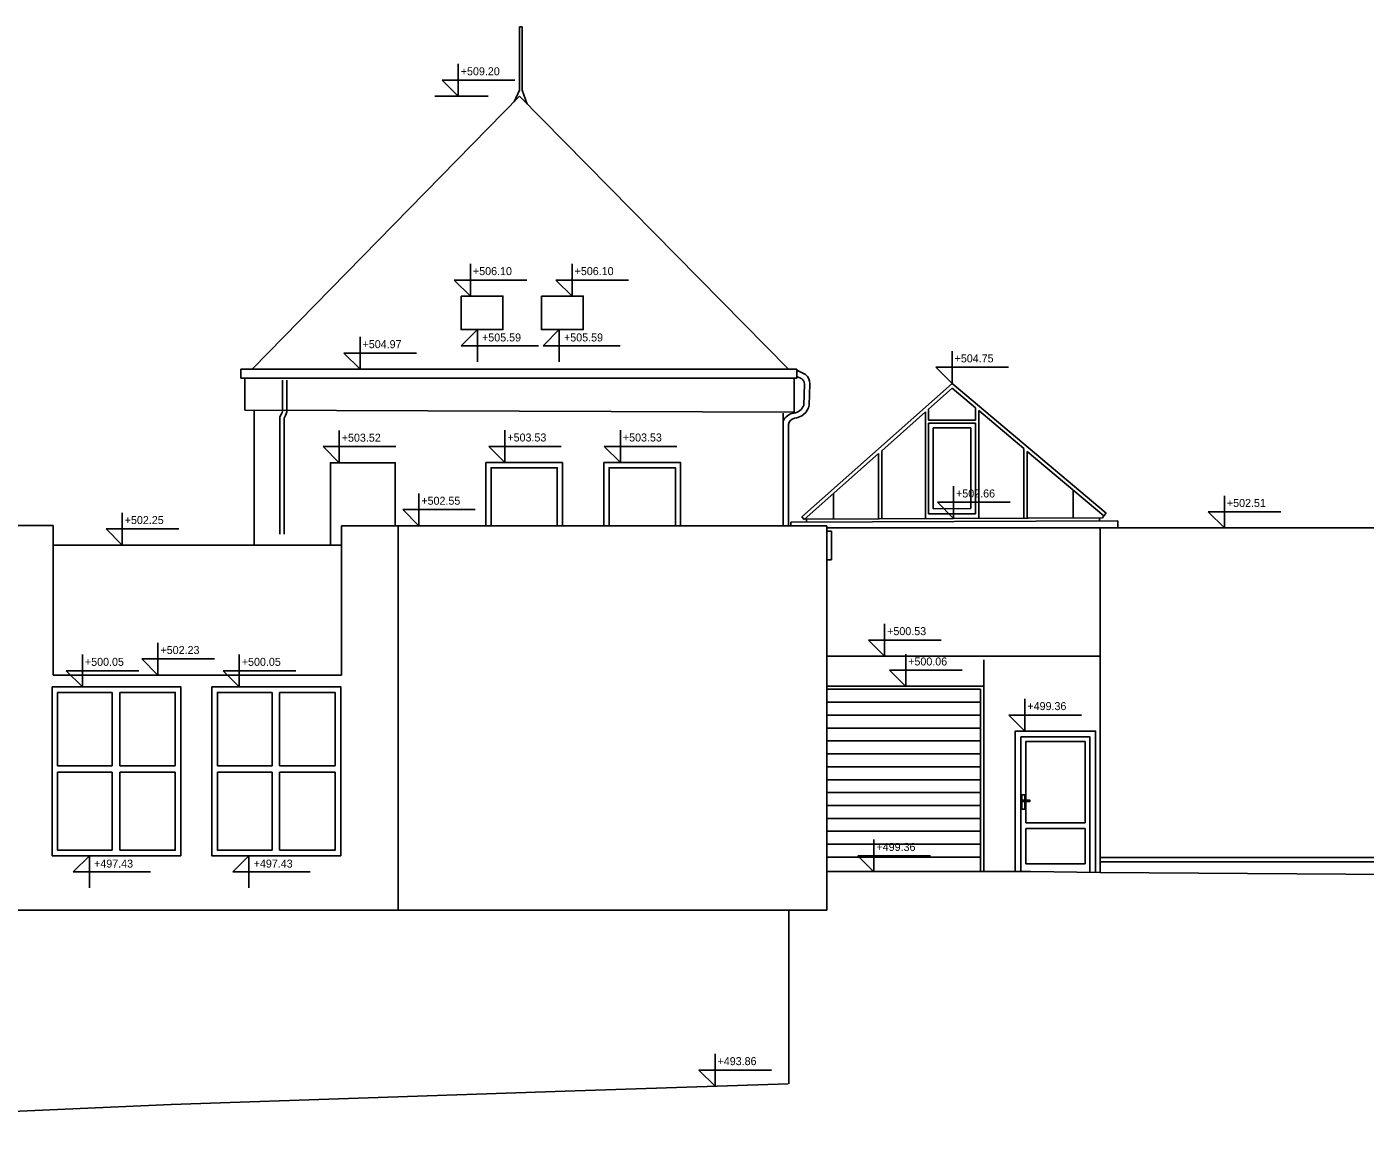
# Model space of a CAD drawing. Extents: x 224 to 311.2, y 493.1 to 511.4.
# Drawn here: x 243.47 to 264.21, y 493.15 to 510.28 of the extents above; entities that cross this region are included whole.
import ezdxf

# ---------------------------------------------------------------- set-up
doc = ezdxf.new("R2010")
doc.units = 0
for name, color, linetype in [('antena', 7, 'Continuous'), ('dvere', 7, 'Continuous'), ('okap', 7, 'Continuous'), ('okna', 7, 'Continuous'), ('strecha_sikma', 7, 'Continuous'), ('svetlik', 7, 'Continuous'), ('teren', 7, 'Continuous'), ('zakl_tenka', 7, 'Continuous'), ('zebrik', 7, 'Continuous'), ('znaceni', 7, 'Continuous')]:
    doc.layers.add(name, color=color, linetype=linetype)

msp = doc.modelspace()

# ---------------------------------------------------------------- linework, layer by layer
at = {"layer": 'antena'}
for p, q in [((251.102, 509.297), (251.102, 510.277)), ((251.142, 510.277), (251.142, 509.297)), ((251.017, 509.115), (251.102, 509.297)), ((251.142, 509.297), (251.222, 509.076))]:
    msp.add_line(p, q, dxfattribs=at)
at = {"layer": 'dvere'}
for p, q in [((257.511, 504.062), (257.511, 502.809)), ((257.511, 504.062), (258.096, 504.062)), ((258.096, 504.062), (258.096, 502.811)), ((258.096, 502.811), (257.511, 502.809)), ((255.862, 500.011), (258.244, 500.011)), ((258.244, 500.011), (258.244, 497.186)), ((255.862, 499.811), (258.244, 499.811)), ((255.862, 499.611), (258.244, 499.611)), ((255.862, 499.411), (258.244, 499.411)), ((255.862, 499.211), (258.244, 499.211)), ((255.862, 499.011), (258.244, 499.011)), ((255.862, 498.811), (258.244, 498.811)), ((255.862, 498.611), (258.244, 498.611)), ((255.862, 498.411), (258.244, 498.411)), ((255.862, 498.211), (258.244, 498.211)), ((255.862, 498.011), (258.244, 498.011)), ((255.862, 497.811), (258.244, 497.811)), ((258.945, 497.945), (259.864, 497.945)), ((258.945, 497.855), (259.864, 497.855)), ((255.862, 497.611), (258.244, 497.611)), ((255.862, 497.411), (258.244, 497.411)), ((258.945, 497.308), (259.864, 497.308))]:
    msp.add_line(p, q, dxfattribs=at)
for points in [[(248.172, 502.246), (248.172, 503.522), (249.175, 503.522), (249.175, 502.545)], [(258.871, 497.186), (258.871, 499.275), (259.939, 499.275), (259.939, 497.176)], [(258.945, 498.296), (258.945, 499.201), (259.864, 499.201), (259.864, 497.945)], [(258.933, 498.272), (258.933, 498.153), (258.887, 498.153), (258.887, 498.377), (258.933, 498.377), (258.933, 498.296)], [(258.945, 497.945), (258.945, 498.272)], [(258.945, 497.308), (258.945, 497.855)], [(259.864, 497.855), (259.864, 497.308)]]:
    msp.add_lwpolyline(points, dxfattribs=at)
msp.add_lwpolyline([(258.901, 498.296), (259.008, 498.296), (259.008, 498.272), (258.901, 498.272)], close=True, dxfattribs=at)
at = {"layer": 'okap'}
for p, q in [((255.399, 504.971), (246.784, 504.971)), ((246.784, 504.971), (246.784, 504.831)), ((255.399, 504.831), (246.784, 504.831)), ((255.399, 504.971), (255.399, 504.831)), ((255.399, 504.958), (255.534, 504.888)), ((255.399, 504.86), (255.478, 504.822)), ((247.43, 504.801), (247.43, 504.342)), ((247.497, 504.801), (247.497, 504.342)), ((255.516, 504.744), (255.505, 504.41)), ((255.602, 504.745), (255.592, 504.412)), ((247.386, 504.197), (247.386, 502.847)), ((247.453, 504.197), (247.453, 502.847)), ((255.27, 504.116), (255.27, 502.545)), ((247.386, 502.847), (247.386, 502.415)), ((247.453, 502.847), (247.453, 502.415))]:
    msp.add_line(p, q, dxfattribs=at)
for centre, radius, start, end in [((255.411, 504.742), 0.104, 0.9921, 50.0332), ((255.411, 504.742), 0.191, 0.9921, 50.0332), ((255.335, 504.471), 0.18, 275.4897, 340.1945), ((255.333, 504.475), 0.266, 275.7615, 346.155), ((247.493, 504.202), 0.108, 145.3455, 182.5261), ((247.282, 504.345), 0.148, 326.2232, 358.5303), ((247.493, 504.202), 0.0403, 145.3455, 182.5261), ((247.282, 504.345), 0.216, 326.2232, 358.5303), ((255.384, 504.073), 0.221, 98.3115, 154.5351), ((255.374, 504.107), 0.104, 97.5209, 175.263)]:
    msp.add_arc(centre, radius, start, end, dxfattribs=at)
at = {"layer": 'okna'}
for p, q in [((244.789, 499.964), (244.789, 498.825)), ((244.906, 499.964), (244.906, 498.825)), ((247.266, 499.964), (247.266, 498.825)), ((247.382, 499.964), (247.382, 498.825)), ((244.789, 498.825), (243.943, 498.825)), ((245.767, 498.825), (244.906, 498.825)), ((247.266, 498.825), (246.419, 498.825)), ((248.244, 498.825), (247.382, 498.825)), ((244.789, 498.73), (243.943, 498.73)), ((244.789, 498.73), (244.789, 497.519)), ((244.906, 498.73), (244.906, 497.519)), ((245.767, 498.73), (244.906, 498.73)), ((247.266, 498.73), (246.419, 498.73)), ((247.266, 498.73), (247.266, 497.519)), ((247.382, 498.73), (247.382, 497.519)), ((248.244, 498.73), (247.382, 498.73))]:
    msp.add_line(p, q, dxfattribs=at)
for points in [[(250.196, 506.103), (250.844, 506.103), (250.844, 505.585), (250.196, 505.585)], [(251.44, 506.103), (252.088, 506.103), (252.088, 505.585), (251.44, 505.585)]]:
    msp.add_lwpolyline(points, close=True, dxfattribs=at)
for points in [[(250.66, 502.545), (250.66, 503.445), (251.687, 503.445), (251.687, 502.545)], [(252.49, 502.545), (252.49, 503.445), (253.517, 503.445), (253.517, 502.545)], [(243.943, 498.825), (243.943, 499.964), (244.789, 499.964)], [(244.906, 499.964), (245.767, 499.964), (245.767, 498.825)], [(246.419, 498.825), (246.419, 499.964), (247.266, 499.964)], [(247.382, 499.964), (248.244, 499.964), (248.244, 498.825)], [(244.789, 497.519), (243.943, 497.519), (243.943, 498.73)], [(245.767, 498.73), (245.767, 497.519), (244.906, 497.519)], [(247.266, 497.519), (246.419, 497.519), (246.419, 498.73)], [(248.244, 498.73), (248.244, 497.519), (247.382, 497.519)]]:
    msp.add_lwpolyline(points, dxfattribs=at)
at = {"layer": 'strecha_sikma'}
for p, q in [((251.1, 509.2), (246.958, 504.971)), ((255.27, 504.971), (251.1, 509.2)), ((243.874, 502.246), (248.344, 502.246)), ((243.874, 500.233), (248.344, 500.233))]:
    msp.add_line(p, q, dxfattribs=at)
at = {"layer": 'svetlik'}
for p, q in [((257.804, 504.751), (255.476, 502.682)), ((257.804, 504.676), (257.44, 504.353)), ((257.804, 504.751), (260.192, 502.742)), ((257.804, 504.676), (258.167, 504.371)), ((257.39, 504.308), (256.713, 503.707)), ((257.39, 504.308), (257.39, 502.657)), ((257.44, 504.353), (257.44, 504.184)), ((258.167, 504.371), (258.167, 504.184)), ((258.217, 504.329), (258.217, 502.66)), ((258.217, 504.329), (258.917, 503.74)), ((257.44, 504.184), (258.167, 504.184)), ((257.44, 504.134), (258.167, 504.134)), ((257.44, 504.134), (257.44, 502.728)), ((258.167, 504.134), (258.167, 502.731)), ((256.663, 503.663), (255.513, 502.64)), ((256.663, 503.663), (256.663, 502.654)), ((256.713, 503.707), (256.713, 502.654)), ((258.917, 503.74), (258.917, 502.663)), ((258.967, 503.698), (258.967, 502.663)), ((258.967, 503.698), (260.155, 502.698)), ((255.965, 503.042), (255.965, 502.651)), ((259.681, 503.097), (259.681, 502.666)), ((260.155, 502.698), (260.192, 502.742)), ((255.476, 502.682), (255.513, 502.64)), ((258.167, 502.731), (257.44, 502.728))]:
    msp.add_line(p, q, dxfattribs=at)
at = {"layer": 'teren'}
for points in [[(255.862, 497.186), (259.02, 497.186), (260.099, 497.175)], [(260.099, 497.175), (263.904, 497.145), (275.27, 497.123), (276.223, 497.121), (292.012, 497.161), (304.698, 497.168)], [(255.262, 493.898), (251.81, 493.787), (245.706, 493.58), (242.767, 493.449), (242.495, 493.427), (237.49, 493.149)]]:
    msp.add_lwpolyline(points, dxfattribs=at)
at = {"layer": 'zakl_tenka'}
for p, q in [((246.844, 504.831), (246.844, 504.338)), ((255.359, 504.831), (255.359, 504.307)), ((255.359, 504.307), (246.844, 504.338)), ((246.992, 504.338), (246.992, 502.246)), ((255.185, 504.29), (255.185, 502.545)), ((236.111, 502.549), (243.874, 502.549)), ((243.874, 502.549), (243.874, 500.233)), ((248.344, 502.545), (248.344, 500.233)), ((255.862, 502.545), (248.344, 502.545)), ((249.221, 502.545), (249.221, 496.588)), ((260.371, 502.623), (255.304, 502.601)), ((255.304, 502.601), (255.304, 502.545)), ((260.133, 502.668), (255.523, 502.649)), ((255.548, 502.651), (255.548, 502.602)), ((255.862, 502.545), (255.862, 496.588)), ((260.086, 502.621), (260.086, 502.668)), ((260.133, 502.668), (260.155, 502.698)), ((260.371, 502.511), (260.371, 502.623)), ((255.862, 502.511), (267.643, 502.511)), ((255.937, 502.464), (255.862, 502.464)), ((255.937, 502.016), (255.937, 502.464)), ((260.099, 502.511), (260.099, 497.175)), ((255.862, 502.016), (255.937, 502.016)), ((255.862, 500.525), (260.099, 500.525)), ((258.294, 500.47), (258.294, 497.186)), ((255.862, 500.061), (258.294, 500.061)), ((260.099, 497.405), (289.987, 497.405)), ((260.099, 497.339), (289.987, 497.339)), ((242.413, 496.588), (255.862, 496.588)), ((255.275, 496.588), (255.275, 493.899))]:
    msp.add_line(p, q, dxfattribs=at)
for points in [[(250.58, 502.545), (250.58, 503.525), (251.767, 503.525), (251.767, 502.545)], [(252.41, 502.545), (252.41, 503.525), (253.597, 503.525), (253.597, 502.545)], [(258.783, 497.186), (258.783, 499.363), (260.027, 499.363), (260.027, 497.176)]]:
    msp.add_lwpolyline(points, dxfattribs=at)
for points in [[(243.857, 500.05), (245.853, 500.05), (245.853, 497.433), (243.857, 497.433)], [(246.333, 500.05), (248.33, 500.05), (248.33, 497.433), (246.333, 497.433)]]:
    msp.add_lwpolyline(points, close=True, dxfattribs=at)
at = {"layer": 'zebrik'}
msp.add_line((251.102, 510.277), (251.142, 510.277), dxfattribs=at)
at = {"layer": 'znaceni'}
for p, q in [((250.152, 509.7), (250.152, 509.2)), ((250.152, 509.45), (249.902, 509.45)), ((249.902, 509.45), (250.152, 509.2)), ((250.152, 509.45), (251.027, 509.45)), ((250.152, 509.2), (250.152, 509.45)), ((250.613, 509.2), (249.79, 509.2)), ((250.341, 506.603), (250.341, 506.103)), ((251.916, 506.603), (251.916, 506.103)), ((250.341, 506.353), (250.091, 506.353)), ((250.091, 506.353), (250.341, 506.103)), ((250.341, 506.353), (251.216, 506.353)), ((250.341, 506.103), (250.341, 506.353)), ((251.916, 506.353), (251.666, 506.353)), ((251.666, 506.353), (251.916, 506.103)), ((251.916, 506.353), (252.791, 506.353)), ((251.916, 506.103), (251.916, 506.353)), ((248.631, 505.471), (248.631, 504.971)), ((250.198, 505.335), (250.448, 505.585)), ((250.448, 505.085), (250.448, 505.585)), ((251.468, 505.335), (251.718, 505.585)), ((251.718, 505.085), (251.718, 505.585)), ((250.448, 505.335), (250.198, 505.335)), ((250.448, 505.335), (251.393, 505.335)), ((251.718, 505.335), (251.468, 505.335)), ((251.718, 505.335), (252.663, 505.335)), ((257.804, 505.251), (257.804, 504.751)), ((248.631, 505.221), (248.381, 505.221)), ((248.381, 505.221), (248.631, 504.971)), ((248.631, 505.221), (249.506, 505.221)), ((248.631, 504.971), (248.631, 505.221)), ((257.804, 505.001), (257.554, 505.001)), ((257.554, 505.001), (257.804, 504.751)), ((257.804, 504.751), (257.804, 505.001)), ((257.804, 505.001), (258.679, 505.001)), ((248.309, 504.022), (248.309, 503.522)), ((250.874, 504.025), (250.874, 503.525)), ((252.664, 504.025), (252.664, 503.525)), ((250.874, 503.775), (250.624, 503.775)), ((250.624, 503.775), (250.874, 503.525)), ((250.874, 503.775), (251.749, 503.775)), ((250.874, 503.525), (250.874, 503.775)), ((252.664, 503.775), (252.414, 503.775)), ((252.414, 503.775), (252.664, 503.525)), ((252.664, 503.775), (253.539, 503.775)), ((252.664, 503.525), (252.664, 503.775)), ((248.309, 503.772), (248.059, 503.772)), ((248.059, 503.772), (248.309, 503.522)), ((248.309, 503.772), (249.184, 503.772)), ((248.309, 503.522), (248.309, 503.772)), ((257.828, 503.159), (257.828, 502.659)), ((249.541, 503.045), (249.541, 502.545)), ((262.023, 503.011), (262.023, 502.511)), ((244.945, 502.746), (244.945, 502.246)), ((249.541, 502.795), (249.291, 502.795)), ((249.291, 502.795), (249.541, 502.545)), ((249.541, 502.795), (250.416, 502.795)), ((249.541, 502.545), (249.541, 502.795)), ((257.828, 502.909), (257.578, 502.909)), ((257.578, 502.909), (257.828, 502.659)), ((257.828, 502.659), (257.828, 502.909)), ((257.828, 502.909), (258.703, 502.909)), ((262.023, 502.761), (261.773, 502.761)), ((261.773, 502.761), (262.023, 502.511)), ((262.023, 502.511), (262.023, 502.761)), ((262.023, 502.761), (262.898, 502.761)), ((244.945, 502.496), (244.695, 502.496)), ((244.695, 502.496), (244.945, 502.246)), ((244.945, 502.496), (245.82, 502.496)), ((244.945, 502.246), (244.945, 502.496)), ((256.759, 501.025), (256.759, 500.525)), ((245.499, 500.733), (245.499, 500.233)), ((256.759, 500.775), (256.509, 500.775)), ((256.509, 500.775), (256.759, 500.525)), ((256.759, 500.525), (256.759, 500.775)), ((256.759, 500.775), (257.634, 500.775)), ((244.328, 500.55), (244.328, 500.05)), ((245.499, 500.483), (245.249, 500.483)), ((245.249, 500.483), (245.499, 500.233)), ((245.499, 500.483), (246.374, 500.483)), ((245.499, 500.233), (245.499, 500.483)), ((246.759, 500.55), (246.759, 500.05)), ((257.086, 500.556), (257.086, 500.056)), ((244.328, 500.3), (244.078, 500.3)), ((244.078, 500.3), (244.328, 500.05)), ((244.328, 500.3), (245.203, 500.3)), ((244.328, 500.05), (244.328, 500.3)), ((246.759, 500.3), (246.509, 500.3)), ((246.509, 500.3), (246.759, 500.05)), ((246.759, 500.3), (247.634, 500.3)), ((246.759, 500.05), (246.759, 500.3)), ((257.086, 500.306), (256.836, 500.306)), ((256.836, 500.306), (257.086, 500.056)), ((257.086, 500.056), (257.086, 500.306)), ((257.086, 500.306), (257.961, 500.306)), ((258.932, 499.863), (258.932, 499.363)), ((258.932, 499.613), (258.682, 499.613)), ((258.682, 499.613), (258.932, 499.363)), ((258.932, 499.363), (258.932, 499.613)), ((258.932, 499.613), (259.807, 499.613)), ((256.594, 497.682), (256.594, 497.182)), ((244.186, 497.183), (244.436, 497.433)), ((244.436, 496.933), (244.436, 497.433)), ((246.659, 497.183), (246.909, 497.433)), ((246.909, 496.933), (246.909, 497.433)), ((256.594, 497.432), (256.344, 497.432)), ((256.344, 497.432), (256.594, 497.182)), ((256.594, 497.182), (256.594, 497.432)), ((256.594, 497.432), (257.469, 497.432)), ((244.436, 497.183), (244.186, 497.183)), ((244.436, 497.183), (245.382, 497.183)), ((246.909, 497.183), (246.659, 497.183)), ((246.909, 497.183), (247.855, 497.183)), ((254.131, 494.362), (254.131, 493.862)), ((254.131, 494.112), (253.881, 494.112)), ((253.881, 494.112), (254.131, 493.862)), ((254.131, 494.112), (255.006, 494.112)), ((254.131, 493.862), (254.131, 494.112))]:
    msp.add_line(p, q, dxfattribs=at)

# ---------------------------------------------------------------- texts
for s, p in [('+509.20', (250.191, 509.525)), ('+506.10', (250.38, 506.429)), ('+506.10', (251.955, 506.429)), ('+505.59', (250.521, 505.401)), ('+505.59', (251.791, 505.401)), ('+504.97', (248.669, 505.297)), ('+504.75', (257.843, 505.077)), ('+503.52', (248.347, 503.848)), ('+503.53', (250.913, 503.851)), ('+503.53', (252.703, 503.851)), ('+502.55', (249.58, 502.871)), ('+502.66', (257.866, 502.984)), ('+502.51', (262.062, 502.836)), ('+502.25', (244.984, 502.572)), ('+500.53', (256.798, 500.851)), ('+502.23', (245.538, 500.558)), ('+500.05', (244.367, 500.375)), ('+500.05', (246.798, 500.375)), ('+500.06', (257.124, 500.381)), ('+499.36', (258.971, 499.689)), ('+499.36', (256.633, 497.507)), ('+497.43', (244.509, 497.249)), ('+497.43', (246.982, 497.249)), ('+493.86', (254.17, 494.188))]:
    msp.add_text(s, height=0.124, dxfattribs=at).set_placement(p)

doc.saveas('drawing.dxf')
